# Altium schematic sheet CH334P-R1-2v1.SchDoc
size 209 x 148 mm; PageSetup: Record=PageOptions¦CenterHorizontal=True¦CenterVertical=True¦PrintScale=0.88¦XCorrection=1.00¦YCorrection=1.00¦PrintKind=1¦BorderSize=5000000¦LeftOffset=0¦BottomOffset=0¦Orientation=2¦PaperLength=1000¦PaperWidth=1000¦Scale=100¦PaperSource=7¦PrintQuality=-4¦MediaType=1¦DitherType=10¦PaperKind=16 开 195x270¦PrintScaleMode=1
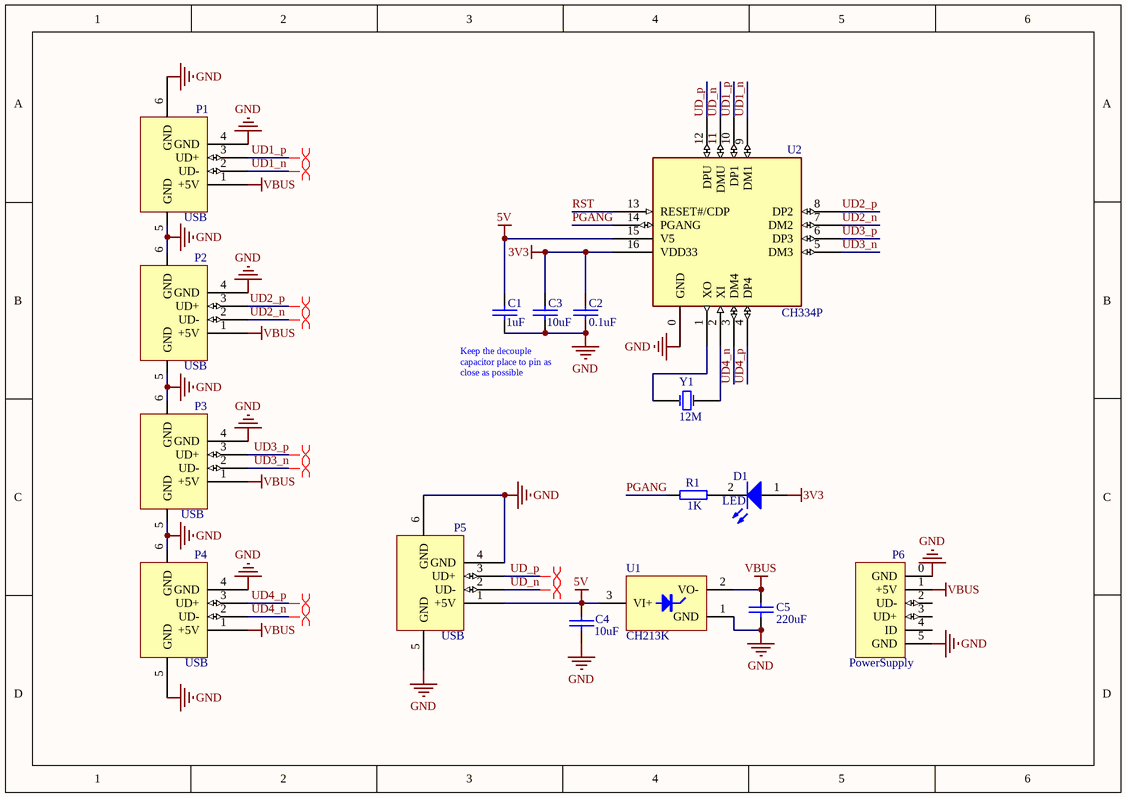
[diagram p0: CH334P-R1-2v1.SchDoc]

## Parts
C1  1uF  [0603_C]
C2  0.1uF  [0603_C]
C3  10uF  [0603_C]
C4  10uF  [0603_C]
C5  220uF  [CD0.1]
D1  LED  [0603+]
P1  USB  [USB2.0-A-F-TH_4P-V_13.7mm]
P2  USB  [USB2.0-A-F-TH_4P-V_13.7mm]
P3  USB  [USB2.0-A-F-TH_4P-V_13.7mm]
P4  USB  [USBAF]
P5  USB  [USBAF]
P6  PowerSupply  [USBMICROB-02-GXPX-A1T2]
R1  1K  [0603_R]
U1  CH213K  [SOT-23-3]
U2  CH334P  [QFN16_3X3]
Y1  12M  [XT_AT49]

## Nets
3V3: C2.1 C3.1 D1.1(A) U2.16(VDD33)
5V: C1.1 C4.1 P5.1(+5V) U1.3(VI+) U2.15(V5)
GND: C1.2 C2.2 C3.2 C4.2 C5.2 P1.4(GND) P1.5(GND) P1.6(GND) P2.4(GND) P2.5(GND) P2.6(GND) P3.4(GND) P3.5(GND) P3.6(GND) P4.4(GND) P4.5(GND) P4.6(GND) P5.4(GND) P5.5(GND) P5.6(GND) P6.0(GND) P6.5(GND) U1.1(GND) U2.0(GND)
VBUS: C5.1 P1.1(+5V) P2.1(+5V) P3.1(+5V) P4.1(+5V) P6.1(+5V) U1.2(VO-)
PGANG: R1.1 U2.14(PGANG)
RST: U2.13(RESET#/CDP)
UD1_n: P1.2(UD-) U2.9(DM1)
UD1_p: P1.3(UD+) U2.10(DP1)
UD2_n: P2.2(UD-) U2.7(DM2)
UD2_p: P2.3(UD+) U2.8(DP2)
UD3_n: P3.2(UD-) U2.5(DM3)
UD3_p: P3.3(UD+) U2.6(DP3)
UD4_n: P4.2(UD-) U2.3(DM4)
UD4_p: P4.3(UD+) U2.4(DP4)
UD_n: P5.2(UD-) U2.11(DMU)
UD_p: P5.3(UD+) U2.12(DPU)
NetD1_2: D1.2(K) R1.2
NetU2_1: U2.1(XO) Y1.1(OSC1)
NetU2_2: U2.2(XI) Y1.2(OSC2)

Not connected (* = marked no-connect by the designer): P6 2(UD-) 3(UD+) 4(ID)

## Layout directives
differential pair: UD1_n, UD1_p, UD2_n, UD2_p, UD3_n, UD3_p, UD4_n, UD4_p, UD_n, UD_p

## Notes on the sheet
- Keep the decouple capacitor place to pin as close as possible

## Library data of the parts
C1-C5 = CAP: Capacitor
D1 = LED: Typical INFRARED GaAs LED
P1-P5 = USB: USB Port
P6 = MicroUSB: MicroUSB Port
R1 = RES
U1 = CH213K: Ideal Diode 5V*1A
U2 = CH334P: 4 ports High-Speed USB MTT Hub
Y1 = XTAL: Crystal Oscillator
